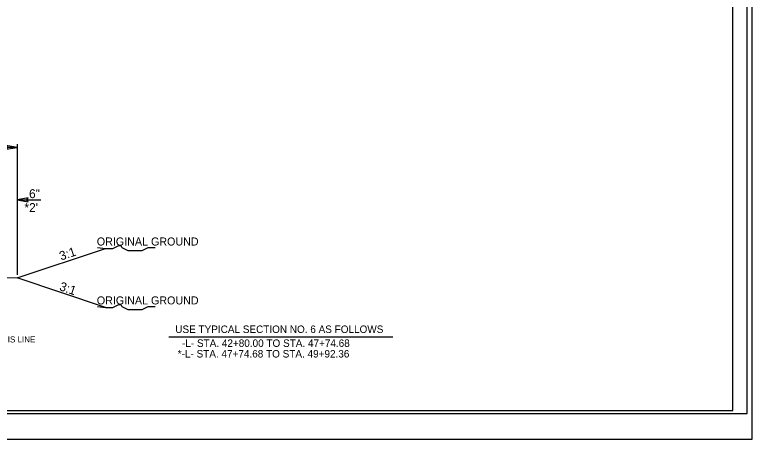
# Model space of a CAD drawing. Extents: x 958711 to 962106, y 831169 to 840840.
# Drawn here: x 959750 to 960395, y 837291 to 837662 of the extents above; entities that cross this region are included whole.
import ezdxf

# ---------------------------------------------------------------- set-up
doc = ezdxf.new("R2010")
doc.units = 0
for name, color, linetype in [('Old_Level_1', 7, 'Continuous'), ('Old_Level_11', 7, 'Continuous'), ('Old_Level_21', 7, 'Continuous'), ('Old_Level_3', 7, 'Continuous'), ('Sheet Plot Border Inside CELL', 7, 'Continuous'), ('Sheet Plot Border Outside CELL', 7, 'Continuous'), ('Sheet Typical CELL', 7, 'Continuous')]:
    doc.layers.add(name, color=color, linetype=linetype)

msp = doc.modelspace()

# ---------------------------------------------------------------- linework, layer by layer
at = {"layer": 'Old_Level_1'}
for p, q in [((959752.42, 837546.02), (959686.38, 837546.02)), ((959752.42, 837548.76), (959752.42, 837434.64)), ((959752.42, 837500.2), (959773.08, 837500.2)), ((959752.42, 837431.94), (959829.6, 837457.67)), ((959752.42, 837431.94), (959689.45, 837431.31)), ((959829.6, 837406.21), (959752.42, 837431.94)), ((959884.8, 837380.4), (960080.74, 837380.4))]:
    msp.add_line(p, q, dxfattribs=at)
at = {"layer": 'Old_Level_11'}
for points in [[(959742.81, 837544.37), (959752.42, 837546.02), (959742.76, 837547.73), (959743.98, 837546.02)], [(959762.02, 837501.86), (959752.42, 837500.2), (959762.08, 837498.49), (959760.85, 837500.2)]]:
    msp.add_lwpolyline(points, close=True, dxfattribs=at)
at = {"layer": 'Old_Level_21'}
for points in [[(959822.51, 837458.55), (959829.6, 837457.67), (959831.38, 837457.67), (959834.04, 837457.67), (959835.82, 837457.67), (959837.58, 837458.55), (959839.36, 837459.45), (959841.13, 837460.33), (959842.91, 837460.33), (959843.81, 837458.55), (959845.57, 837457.67), (959847.34, 837456.78), (959849.11, 837455.9), (959850.89, 837455.9), (959852.66, 837455.9), (959854.44, 837455.9), (959856.21, 837455.9), (959857.98, 837455.9), (959859.75, 837455.9), (959861.53, 837455.9), (959863.3, 837456.78), (959865.07, 837457.67), (959866.84, 837458.55), (959869.51, 837458.55), (959871.28, 837458.55), (959873.06, 837458.55)], [(959822.51, 837407.09), (959829.6, 837406.21), (959831.38, 837406.21), (959834.04, 837406.21), (959835.82, 837406.21), (959837.58, 837407.09), (959839.36, 837407.99), (959841.13, 837408.87), (959842.91, 837408.87), (959843.81, 837407.09), (959845.57, 837406.21), (959847.34, 837405.31), (959849.11, 837404.44), (959850.89, 837404.44), (959852.66, 837404.44), (959854.44, 837404.44), (959856.21, 837404.44), (959857.98, 837404.44), (959859.75, 837404.44), (959861.53, 837404.44), (959863.3, 837405.31), (959865.07, 837406.21), (959866.84, 837407.09), (959869.51, 837407.09), (959871.28, 837407.09), (959873.06, 837407.09)]]:
    msp.add_lwpolyline(points, dxfattribs=at)
at = {"layer": 'Sheet Plot Border Inside CELL'}
msp.add_lwpolyline([(960390.3, 838368.62), (958723.8, 838368.62), (958723.8, 837313.52), (960390.3, 837313.52)], close=True, dxfattribs=at)
at = {"layer": 'Sheet Plot Border Outside CELL'}
msp.add_lwpolyline([(960394.8, 838391.07), (958710.8, 838391.07), (958710.8, 837291.07), (960394.8, 837291.07)], close=True, dxfattribs=at)
at = {"layer": 'Sheet Typical CELL'}
msp.add_lwpolyline([(960377.8, 838366.07), (958877.8, 838366.07), (958877.8, 837316.07), (960377.8, 837316.07)], close=True, dxfattribs=at)

# ---------------------------------------------------------------- texts
at = {"layer": 'Old_Level_1'}
for s, height, p in [('USE TYPICAL SECTION NO. 6 AS FOLLOWS', 6.5088, (959890.54, 837383.92)), ('GRADE TO THIS LINE', 5.2473, (959696.15, 837375.63)), ('-L- STA. 42+80.00 TO STA. 47+74.68', 6.5088, (959896.44, 837371.74)), ('*-L- STA. 47+74.68 TO STA. 49+92.36', 6.5088, (959892.72, 837362.46))]:
    msp.add_text(s, height=height, dxfattribs=at).set_placement(p)
at = {"layer": 'Old_Level_21'}
for p in [(959821.97, 837460.3), (959821.97, 837408.84)]:
    msp.add_text('ORIGINAL GROUND', height=7, dxfattribs=at).set_placement(p)
at = {"layer": 'Old_Level_3'}
for s, p in [('6"', (959762.73, 837501.68)), ("*2'", (959758.71, 837489.52))]:
    msp.add_text(s, height=7.801, dxfattribs=at).set_placement(p)
for rotation, p in [(18.43485, (959790.72, 837447.12)), (341.04545, (959788.66, 837421.44))]:
    msp.add_text('3:1', height=7.801, rotation=rotation, dxfattribs=at).set_placement(p)

doc.saveas('drawing.dxf')
